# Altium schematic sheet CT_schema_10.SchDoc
size 274 x 160 mm
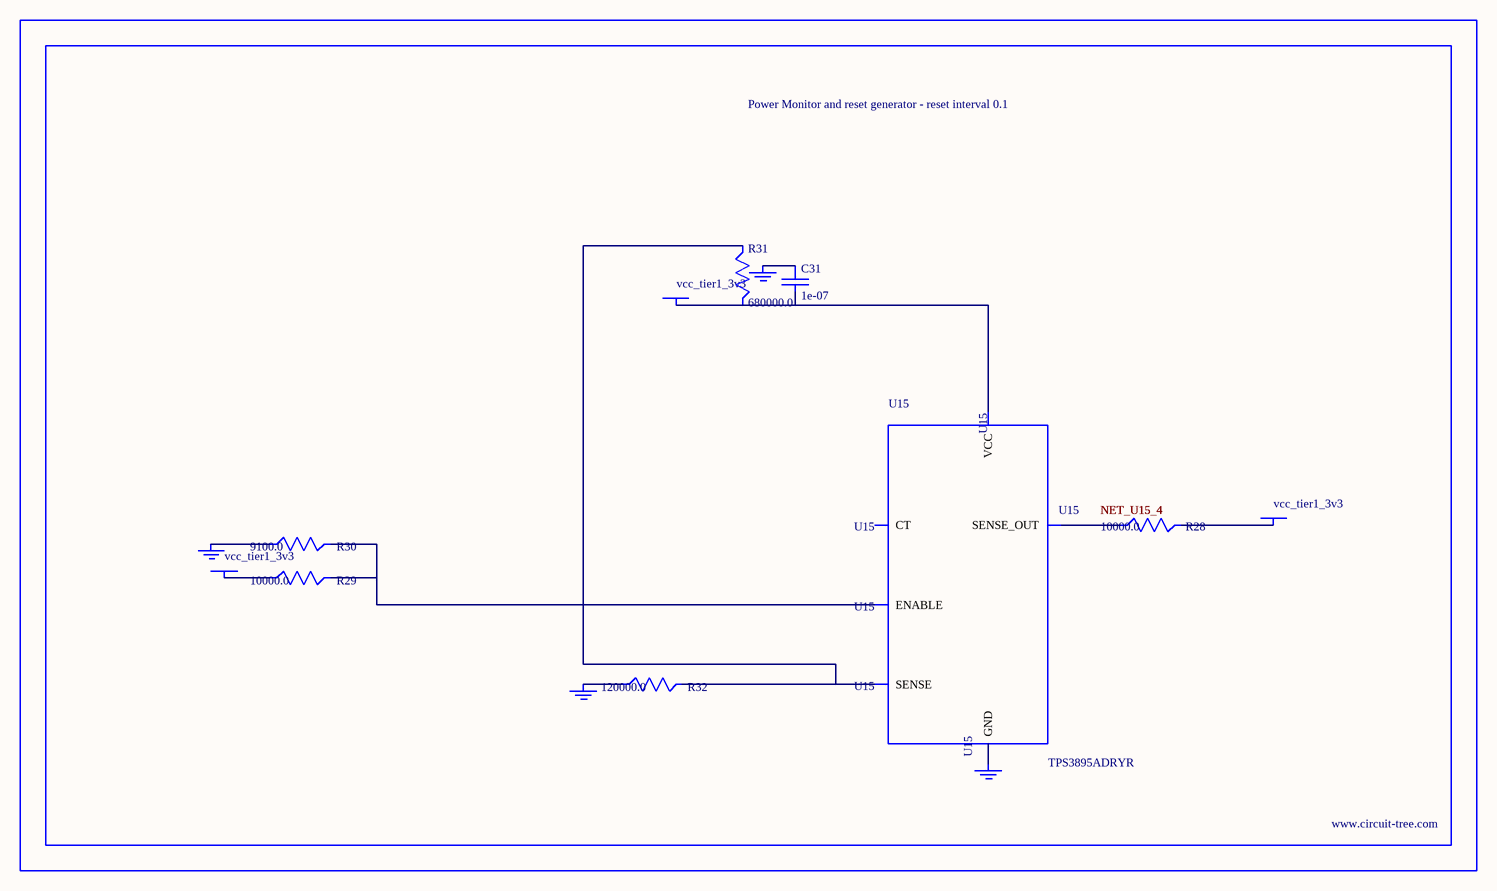
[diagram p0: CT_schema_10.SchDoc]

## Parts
BORDER9  (no value)
C31  1e-07  [C0402]
GND_INSTANCE_9_0  (no value)
GND_INSTANCE_9_1  (no value)
GND_INSTANCE_9_2  (no value)
GND_INSTANCE_9_3  (no value)
POWER_INSTANCE_9_0  vcc_tier1_3v3
POWER_INSTANCE_9_1  vcc_tier1_3v3
POWER_INSTANCE_9_2  vcc_tier1_3v3
R28  10000.0  [R0603]
R29  10000.0  [R0603]
R30  9100.0  [R0603]
R31  680000.0  [R0603]
R32  120000.0  [R0603]
U15  TPS3895ADRYR  [SON-6]

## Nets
NetC31_1: C31.1 GND_INSTANCE_9_2.0(GND)
NetC31_2: C31.2 POWER_INSTANCE_9_2.0(PWR) R31.2 U15.6(VCC)
NetGND_INSTANCE_9_0_0: GND_INSTANCE_9_0.0(GND) R30.1
NetGND_INSTANCE_9_1_0: GND_INSTANCE_9_1.0(GND) R32.1
NetGND_INSTANCE_9_3_0: GND_INSTANCE_9_3.0(GND) U15.2(GND)
NetPOWER_INSTANCE_9_0_0: POWER_INSTANCE_9_0.0(PWR) R29.1
NetPOWER_INSTANCE_9_1_0: POWER_INSTANCE_9_1.0(PWR) R28.2
NetR28_1: R28.1 U15.4(SENSE_OUT)
NetR29_2: R29.2 R30.2 U15.1(ENABLE)
NetR31_1: R31.1 R32.2 U15.3(SENSE)

Not connected (* = marked no-connect by the designer): U15 5(CT)

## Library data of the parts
BORDER9 = BORDER_PAGE9
C31 = C0402C104K3RACTU
GND_INSTANCE_9_0-GND_INSTANCE_9_3 = GND
POWER_INSTANCE_9_0-POWER_INSTANCE_9_2 = PWR
R28 R29 = RC0603JR-0710KL
R30 = RC0603JR-079K1L
R31 = RC0603JR-07680KL
R32 = RC0603JR-07120KL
